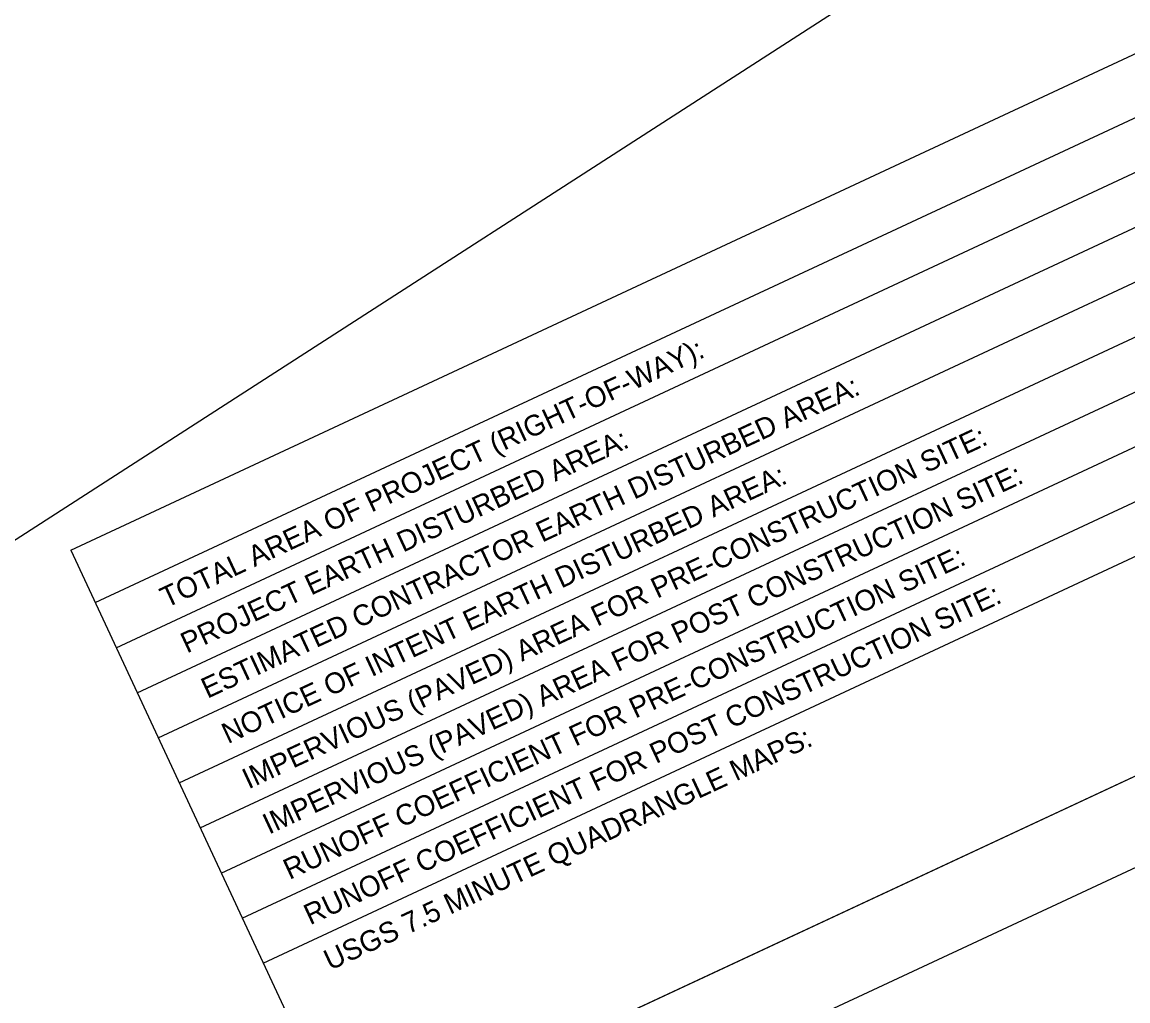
# Model space of a CAD drawing. Extents: x -310467766 to 17062430, y -322263100 to 8322522.
# Drawn here: x 1397464 to 1399466, y 570590 to 572361 of the extents above; entities that cross this region are included whole.
import ezdxf

# ---------------------------------------------------------------- set-up
doc = ezdxf.new("R2010")
doc.units = 0
for name, color, linetype in [('Level 40', 7, 'Continuous'), ('SC_Scratch1', 7, 'Continuous'), ('SH_Border', 7, 'Continuous'), ('SH_Cut_Line', 7, 'Continuous')]:
    doc.layers.add(name, color=color, linetype=linetype)

msp = doc.modelspace()

# ---------------------------------------------------------------- linework, layer by layer
at = {"layer": 'Level 40'}
for p, q in [((1397552.3, 571405.7), (1402393.6, 573663.2)), ((1397596.7, 571310.5), (1402438, 573568)), ((1398053.1, 570331.7), (1402894.4, 572589.2)), ((1397634.7, 571228.9), (1400055.4, 572357.7)), ((1397672.8, 571147.4), (1400093.4, 572276.1)), ((1397710.8, 571065.8), (1400131.4, 572194.6)), ((1397748.8, 570984.2), (1400169.5, 572113)), ((1397786.9, 570902.7), (1400207.5, 572031.4)), ((1397824.9, 570821.1), (1400245.5, 571949.9)), ((1397862.9, 570739.5), (1400283.6, 571868.3)), ((1397901, 570658), (1400321.6, 571786.7)), ((1397901, 570658), (1400321.6, 571786.7)), ((1397552.3, 571405.7), (1398053.1, 570331.7))]:
    msp.add_line(p, q, dxfattribs=at)
at = {"layer": 'SC_Scratch1'}
msp.add_lwpolyline([(1392212.4, 573822.1), (1393676.3, 570715.4), (1396857.5, 571041.4), (1399761.2, 572912.7), (1399601.4, 573251.9), (1400998.4, 575913.7), (1400551.7, 577289.3)], close=True, dxfattribs=at)
at = {"layer": 'SH_Border'}
msp.add_lwpolyline([(1391939.2, 574432), (1400639.7, 578489.1), (1403302.2, 572779.4), (1394601.7, 568722.3)], close=True, dxfattribs=at)
at = {"layer": 'SH_Cut_Line'}
msp.add_lwpolyline([(1394257.2, 568396.1), (1403501.6, 572706.8), (1400712.3, 578688.5), (1391467.9, 574377.8)], close=True, dxfattribs=at)

# ---------------------------------------------------------------- texts
at = {"layer": 'Level 40'}
for s, p in [('TOTAL AREA OF PROJECT (RIGHT-OF-WAY):', (1397725.6, 571300.3)), ('ESTIMATED CONTRACTOR EARTH DISTURBED AREA:', (1397799.9, 571136.3)), ('PROJECT EARTH DISTURBED AREA:', (1397762.7, 571218.3)), ('IMPERVIOUS (PAVED) AREA FOR PRE-CONSTRUCTION SITE:', (1397874.2, 570972.4)), ('NOTICE OF INTENT EARTH DISTURBED AREA:', (1397837, 571054.3)), ('IMPERVIOUS (PAVED) AREA FOR POST CONSTRUCTION SITE:', (1397911.3, 570890.4)), ('RUNOFF COEFFICIENT FOR PRE-CONSTRUCTION SITE:', (1397948.5, 570808.4)), ('RUNOFF COEFFICIENT FOR POST CONSTRUCTION SITE:', (1397985.7, 570726.4)), ('USGS 7.5 MINUTE QUADRANGLE MAPS:', (1398021.9, 570644.1))]:
    msp.add_text(s, height=37.5, rotation=25, dxfattribs=at).set_placement(p)

doc.saveas('drawing.dxf')
